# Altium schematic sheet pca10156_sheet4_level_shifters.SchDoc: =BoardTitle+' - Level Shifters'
size A3; Organization: Nordic Semiconductor; DocumentNumber: 4; SheetNumber: 4; SheetTotal: 8; CompanyName: Nordic Semiconductor; DocumentSize: A4
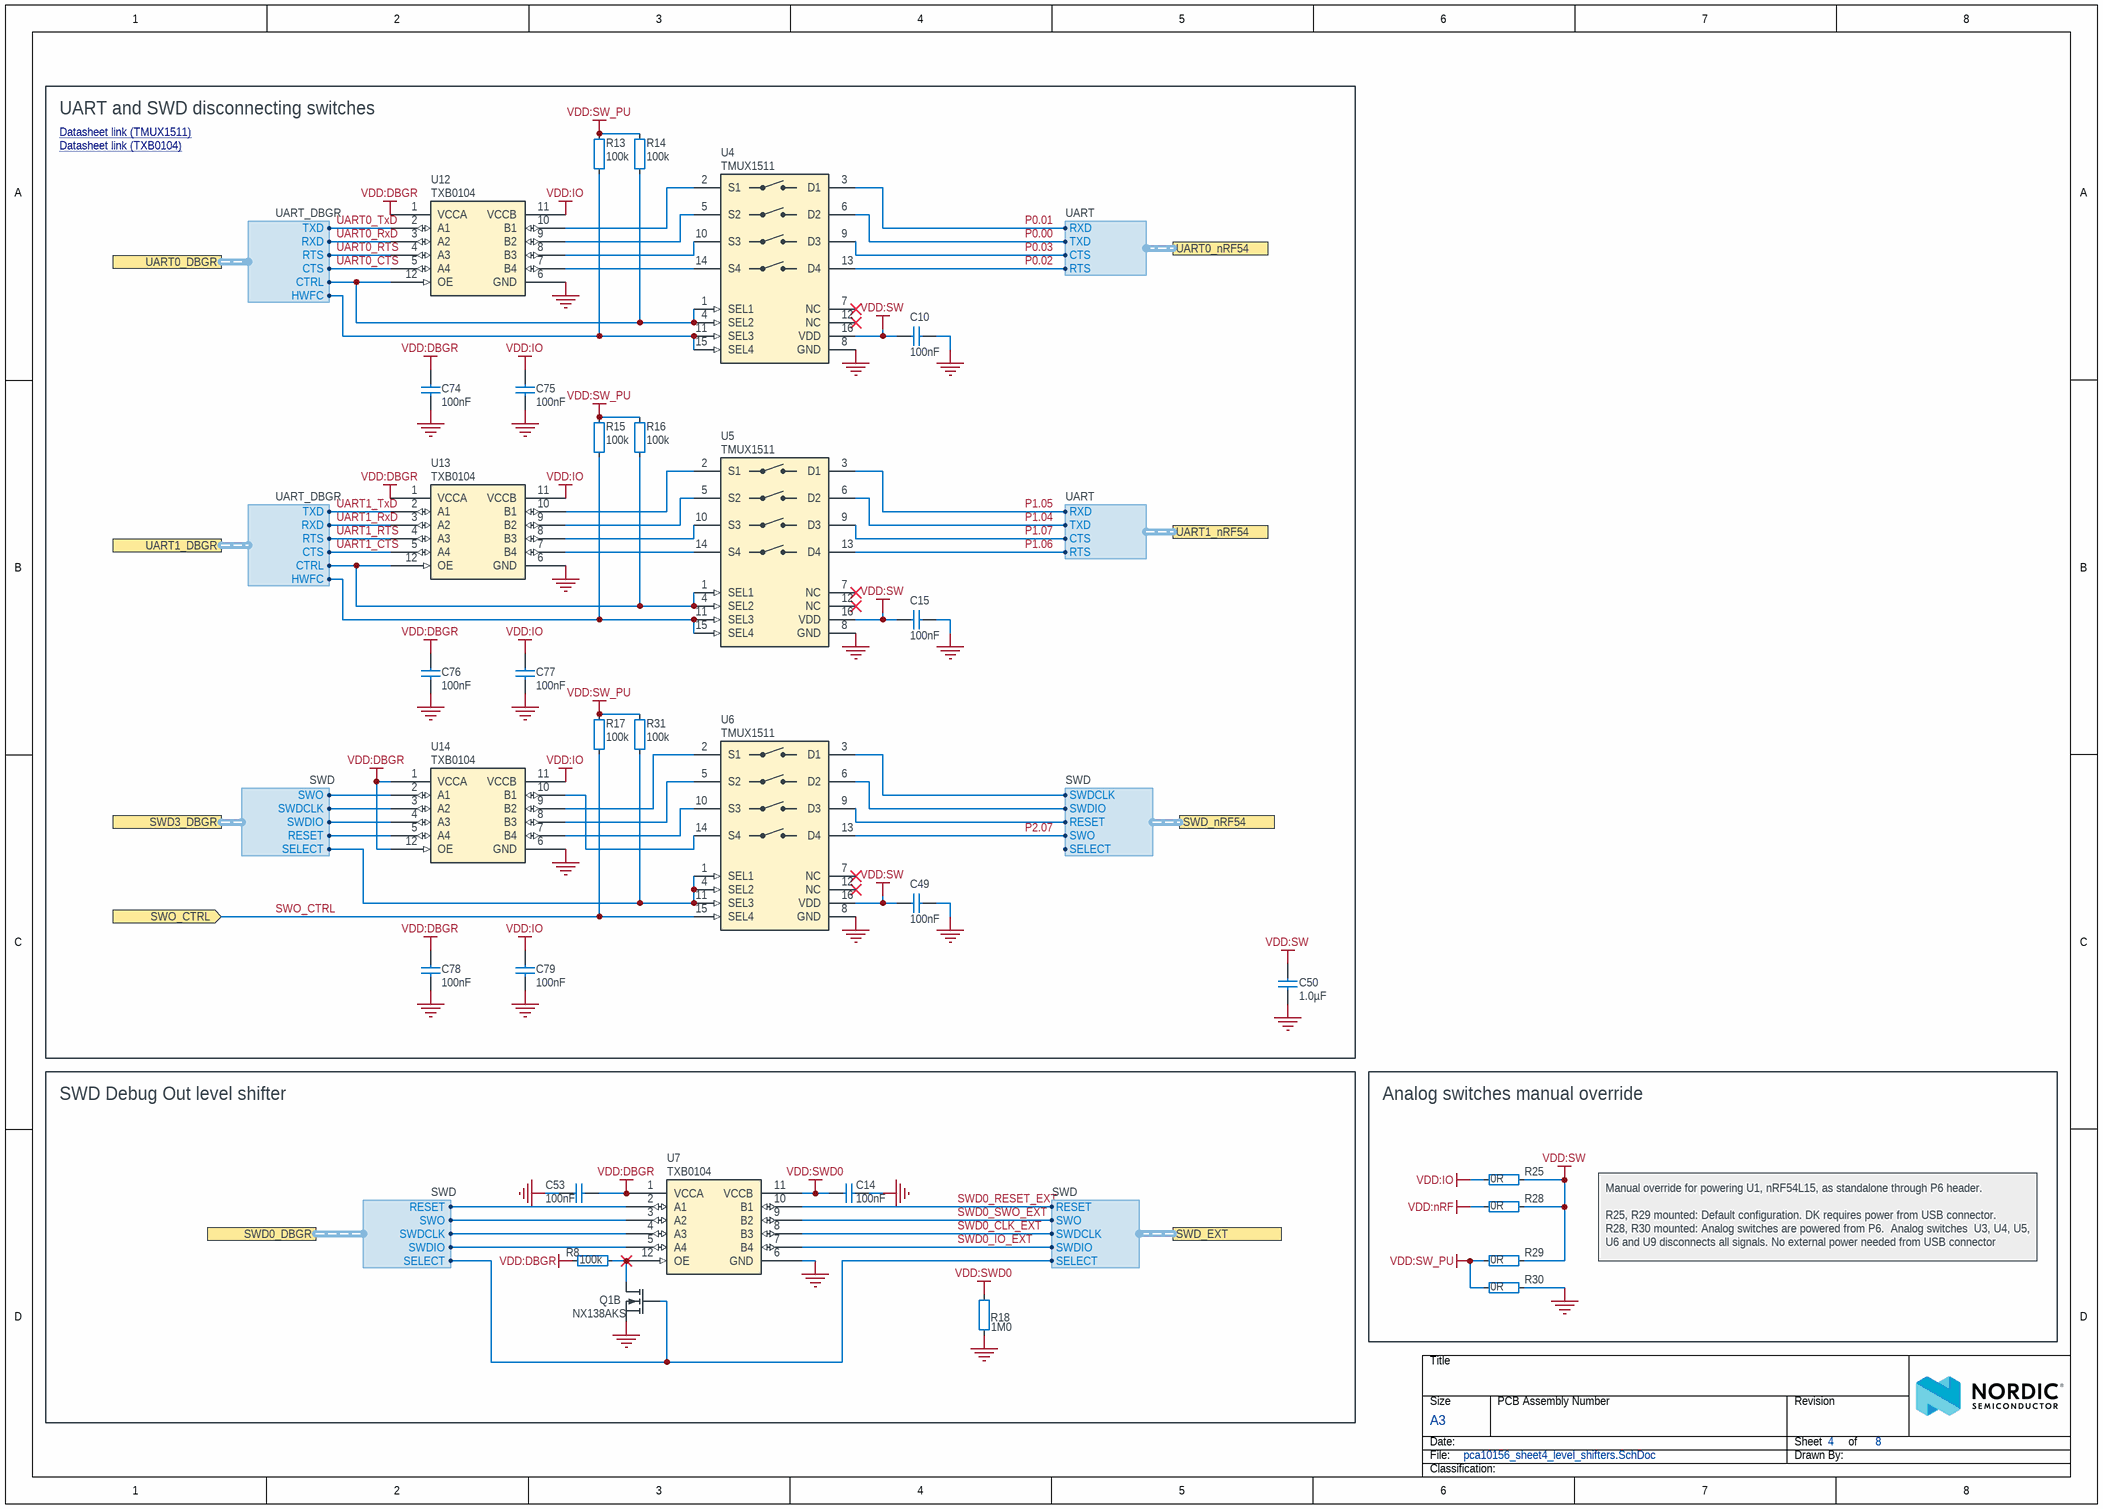
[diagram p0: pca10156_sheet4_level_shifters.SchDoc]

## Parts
C10  100nF  [CAPC0603X03L_C]
C14  100nF  [CAPC0603X03L_C]
C15  100nF  [CAPC0603X03L_C]
C49  100nF  [CAPC0603X03L_C]
C50  1.0µF  [CAPC1005X04L]
C53  100nF  [CAPC0603X03L_C]
C74  100nF  [CAPC0603X03L_C]
C75  100nF  [CAPC0603X03L_C]
C76  100nF  [CAPC0603X03L_C]
C77  100nF  [CAPC0603X03L_C]
C78  100nF  [CAPC0603X03L_C]
C79  100nF  [CAPC0603X03L_C]
Q1  NX138AKS  [TSSOP6]  (part B of 2)
R8  100k  [RESC0603X03L_C]
R13  100k  [RESC0603X03L_C]
R14  100k  [RESC0603X03L_C]
R15  100k  [RESC0603X03L_C]
R16  100k  [RESC0603X03L_C]
R17  100k  [RESC0603X03L_C]
R18  1M0  [RESC0603X03L_C]
R25  0R  [RESC1005X04L]
R28  0R  [RESC1005X04L]
R29  0R  [RESC1005X04L]
R30  0R  [RESC1005X04L]
R31  100k  [RESC0603X03L_C]
U4  TMUX1511  [XQFN40P180X260X50-16N]
U5  TMUX1511  [XQFN40P180X260X50-16N]
U6  TMUX1511  [XQFN40P180X260X50-16N]
U7  TXB0104  [QFN12P40_170X200X55L50X20]
U12  TXB0104  [QFN12P40_170X200X55L50X20]
U13  TXB0104  [QFN12P40_170X200X55L50X20]
U14  TXB0104  [QFN12P40_170X200X55L50X20]

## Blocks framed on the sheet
UART and SWD disconnecting switches: C10 C15 C49 C50 C74-C79 R13-R17 R31 U4-U6 U12-U14
SWD Debug Out level shifter: C14 C53 Q1 R8 R18 U7
Analog switches manual override: R25 R28-R30

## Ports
SWD0_DBGR (harness SWD), SWD3_DBGR (harness SWD), SWD_EXT (harness SWD), SWD_nRF54 (harness SWD), SWO_CTRL (in), UART0_DBGR (harness UART_DBGR), UART0_nRF54 (harness UART), UART1_DBGR (harness UART_DBGR), UART1_nRF54 (harness UART)

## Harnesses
SWD: SWDIO, SWDCLK, SWO, RESET, SELECT
UART: RTS, CTS, RXD, TXD
UART_DBGR: RTS, CTS, RXD, TXD, HWFC, CTRL

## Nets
GND: C10.2 C14.2 C15.2 C49.2 C50.1 C53.1 C74.2 C75.2 C76.2 C77.2 C78.2 C79.2 Q1.4(S2) R18.1 R30.2 U4.8(GND) U5.8(GND) U6.8(GND) U7.6(GND) U12.6(GND) U13.6(GND) U14.6(GND)
VDD:DBGR: C53.2 C74.1 C76.1 C78.1 R8.2 U7.1(VCCA) U12.1(VCCA) U13.1(VCCA) U14.1(VCCA) U14.12(OE)
VDD:IO: C75.1 C77.1 C79.1 R25.1 U12.11(VCCB) U13.11(VCCB) U14.11(VCCB)
VDD:nRF: R28.1
VDD:SW: C10.1 C15.1 C49.1 C50.2 R25.2 R28.2 R29.2 U4.16(VDD) U5.16(VDD) U6.16(VDD)
VDD:SW_PU: R13.1 R14.1 R15.1 R16.1 R17.2 R29.1 R30.1 R31.1
VDD:SWD0: C14.1 R18.2 U7.11(VCCB)
P0.00: U4.6(D2) ; port UART0_nRF54.TXD
P0.01: U4.3(D1) ; port UART0_nRF54.RXD
P0.02: U4.13(D4) ; port UART0_nRF54.RTS
P0.03: U4.9(D3) ; port UART0_nRF54.CTS
P1.04: U5.6(D2) ; port UART1_nRF54.TXD
P1.05: U5.3(D1) ; port UART1_nRF54.RXD
P1.06: U5.13(D4) ; port UART1_nRF54.RTS
P1.07: U5.9(D3) ; port UART1_nRF54.CTS
P2.07: U6.13(D4) ; port SWD_nRF54.SWO
SWD0_CLK_EXT: U7.8(B3) ; port SWD_EXT.SWDCLK
SWD0_IO_EXT: U7.7(B4) ; port SWD_EXT.SWDIO
SWD0_RESET_EXT: U7.10(B1) ; port SWD_EXT.RESET
SWD0_SWO_EXT: U7.9(B2) ; port SWD_EXT.SWO
SWO_CTRL: R17.1 U6.15(SEL4) ; port SWO_CTRL
UART0_CTS: U12.5(A4) ; port UART0_DBGR.CTS
UART0_RTS: U12.4(A3) ; port UART0_DBGR.RTS
UART0_RxD: U12.3(A2) ; port UART0_DBGR.RXD
UART0_TxD: U12.2(A1) ; port UART0_DBGR.TXD
UART1_CTS: U13.5(A4) ; port UART1_DBGR.CTS
UART1_RTS: U13.4(A3) ; port UART1_DBGR.RTS
UART1_RxD: U13.3(A2) ; port UART1_DBGR.RXD
UART1_TxD: U13.2(A1) ; port UART1_DBGR.TXD
NetQ1_3: Q1.3(D2) R8.1 U7.12(OE)
NetQ1_5: Q1.5(G2) ; port SWD0_DBGR.SELECT, port SWD_EXT.SELECT
NetR13_2: R13.2 U4.11(SEL3) U4.15(SEL4) ; port UART0_DBGR.HWFC
NetR14_2: R14.2 U4.1(SEL1) U4.4(SEL2) U12.12(OE) ; port UART0_DBGR.CTRL
NetR15_2: R15.2 U5.11(SEL3) U5.15(SEL4) ; port UART1_DBGR.HWFC
NetR16_2: R16.2 U5.1(SEL1) U5.4(SEL2) U13.12(OE) ; port UART1_DBGR.CTRL
NetR31_2: R31.2 U6.1(SEL1) U6.4(SEL2) U6.11(SEL3) ; port SWD3_DBGR.SELECT
NetU4_2: U4.2(S1) U12.10(B1)
NetU4_5: U4.5(S2) U12.9(B2)
NetU4_10: U4.10(S3) U12.8(B3)
NetU4_14: U4.14(S4) U12.7(B4)
NetU5_2: U5.2(S1) U13.10(B1)
NetU5_5: U5.5(S2) U13.9(B2)
NetU5_10: U5.10(S3) U13.8(B3)
NetU5_14: U5.14(S4) U13.7(B4)
NetU6_2: U6.2(S1) U14.9(B2)
NetU6_3: U6.3(D1) ; port SWD_nRF54.SWDCLK
NetU6_5: U6.5(S2) U14.8(B3)
NetU6_6: U6.6(D2) ; port SWD_nRF54.SWDIO
NetU6_9: U6.9(D3) ; port SWD_nRF54.RESET
NetU6_10: U6.10(S3) U14.7(B4)
NetU6_14: U6.14(S4) U14.10(B1)
NetU7_2: U7.2(A1) ; port SWD0_DBGR.RESET
NetU7_3: U7.3(A2) ; port SWD0_DBGR.SWO
NetU7_4: U7.4(A3) ; port SWD0_DBGR.SWDCLK
NetU7_5: U7.5(A4) ; port SWD0_DBGR.SWDIO
NetU14_2: U14.2(A1) ; port SWD3_DBGR.SWO
NetU14_3: U14.3(A2) ; port SWD3_DBGR.SWDCLK
NetU14_4: U14.4(A3) ; port SWD3_DBGR.SWDIO
NetU14_5: U14.5(A4) ; port SWD3_DBGR.RESET

Not connected (* = marked no-connect by the designer): U4 7(NC)* 12(NC)*; U5 7(NC)* 12(NC)*; U6 7(NC)* 12(NC)*

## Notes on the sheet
- Datasheet link (TMUX1511) <https://www.ti.com/lit/ds/symlink/tmux1511.pdf?ts=1730882090102&ref_url=https%253A%252F%252Fwww.mouser.dk%252F>
- Datasheet link (TXB0104) <https://www.ti.com/lit/ds/symlink/txb0104.pdf?src-supplier=IHS+Markit>
- Manual override for powering U1, nRF54L15, as standalone through P6 header.
  R25, R29 mounted: Default configuration. DK requires power from USB connector.
  R28, R30 mounted: Analog switches are powered from P6.  Analog switches  U3, U4, U5, U6 and U9 disconnects all signals. No external power needed from USB connector

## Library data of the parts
C10 C14 C15 C49 C53 C74-C79 = C0201-100n: Capacitor, X5R, ±10%; Manufacturer: N.A.; Part number IPS: 00000001248, 00000002505; Part number Norautron: 262071862; Part number NEMS: 100200078; Pad Count: 2; Note: 16V; Component Status: Active
C50 = C0402-1µ0-6.3V-X5R-10%: Capacitor, X5R, ±10%, 6.3V; Manufacturer: N.A.; Part number Norautron: 26207137; Part number NEMS: 100200498; Pad Count: 2; Component Status: Active
Q1 = NX138AKS: MOSFET 2N-CH 60V 0.17A TSSOP6 (SOT363); Manufacturer: Nexperia; Manufacturer Part Number: NX138AKSX; Part number NEMS: 101300207; Component Status: Active; Pad Count: 6; Note: N.A.
R8 R13-R17 R31 = R0201-100k: Resistor, ±1%, 0.05W; Manufacturer: N.A.; Part number IPS: 00000001419; Part number Norautron: 26108487; Part number NEMS: 100100080; Note: Chip Res 1%; Pad Count: 2; Component Status: Active
R18 = R0201-1M0: Resistor, ±1%, 0.05W; Manufacturer: N.A.; Part number IPS: 00000001418; Part number Norautron: 26107108; Part number NEMS: 100100093; Component Status: Active; Pad Count: 2; Note: Chip Res 1%
R25 R28-R30 = R0402-0R: Resistor, ±5%, 0.063W; Manufacturer: N.A.; Part number IPS: 00000007128; Part number NEMS: 100100109; Component Status: Active; Pad Count: 2; Note: Chip Res 5%; Artikkelnr Noca: 27049000
U4-U6 = TMUX1511: Low-Capacitance, 1:1 (SPST) 4-Channel, analog switch; Manufacturer: Texas Instruments; Manufacturer Part Number: TMUX1511RSVR; Part number NEMS: 101900847; Component Status: Active; Pad Count: 16; Note: N.A.
U7 U12-U14 = TXB0104RUTR: 4-Bit Bidirectional Level-Shifter/Voltage Translator with Automatic Direction Sensing; Manufacturer: Texas Instruments; Part number NEMS: 101900856; Component Status: Active; Pad Count: 12; Note: Translator, Bidirectional; Artikkelnr Noca: N.A.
